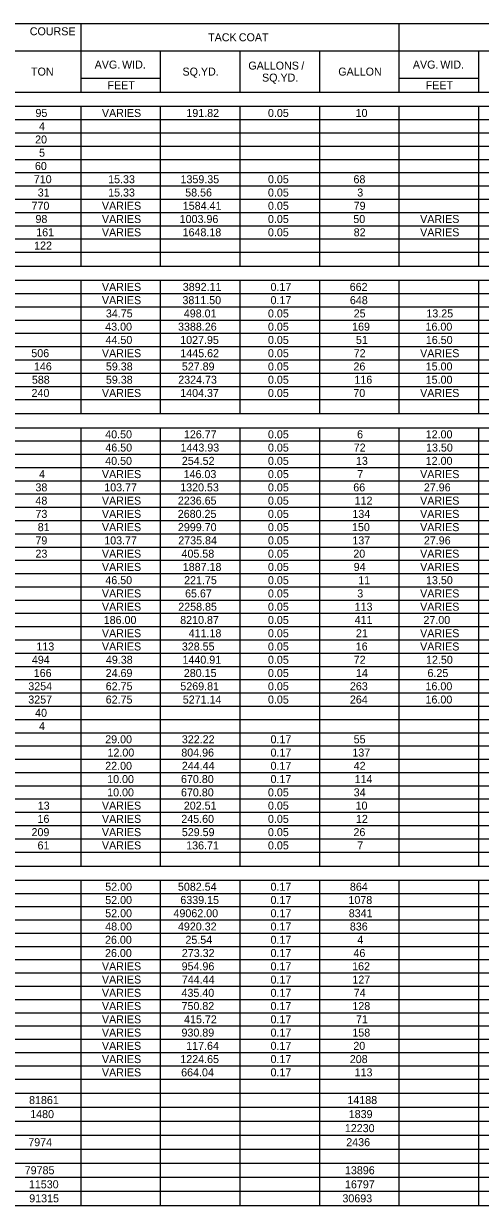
# Model space of a CAD drawing. Extents: x 1226567 to 1228151, y 151309 to 152305.
# Drawn here: x 1226930 to 1227158, y 151665 to 152255 of the extents above; entities that cross this region are included whole.
import ezdxf

# ---------------------------------------------------------------- set-up
doc = ezdxf.new("R2010")
doc.units = 0
doc.layers.add('R_Dimension', color=7, linetype='Continuous')

msp = doc.modelspace()

# ---------------------------------------------------------------- linework, layer by layer
at = {"layer": 'R_Dimension'}
for p, q in [((1226566.84, 152254.68), (1228150.79, 152254.68)), ((1226959.03, 152220.4), (1226959.03, 152254.68)), ((1227117.93, 152220.4), (1227117.93, 152254.68)), ((1226879.58, 152241.04), (1228150.79, 152241.04)), ((1226998.76, 152220.4), (1226998.76, 152241.04)), ((1227038.48, 152220.4), (1227038.48, 152241.04)), ((1227078.21, 152220.4), (1227078.21, 152241.04)), ((1227157.66, 152220.4), (1227157.66, 152241.04)), ((1226959.03, 152227.41), (1226998.76, 152227.41)), ((1227117.93, 152227.41), (1227157.66, 152227.41)), ((1226566.84, 152220.4), (1228150.79, 152220.4)), ((1226566.84, 152220.4), (1228150.79, 152220.4)), ((1226879.58, 152220.4), (1226998.76, 152220.4)), ((1226998.76, 152220.4), (1227157.66, 152220.4)), ((1227157.66, 152220.4), (1227396.01, 152220.4)), ((1226566.84, 152213.39), (1228150.79, 152213.39)), ((1226959.03, 152133.55), (1226959.03, 152213.39)), ((1226998.76, 152133.55), (1226998.76, 152213.39)), ((1227038.48, 152133.55), (1227038.48, 152213.39)), ((1227078.21, 152133.55), (1227078.21, 152213.39)), ((1227117.93, 152133.55), (1227117.93, 152213.39)), ((1227157.66, 152133.55), (1227157.66, 152213.39)), ((1226566.84, 152206.77), (1228150.79, 152206.77)), ((1226566.84, 152200.15), (1228150.79, 152200.15)), ((1226566.84, 152193.53), (1228150.79, 152193.53)), ((1226566.84, 152186.91), (1228150.79, 152186.91)), ((1226566.84, 152180.29), (1228150.79, 152180.29)), ((1226566.84, 152173.67), (1228150.79, 152173.67)), ((1226566.84, 152167.05), (1228150.79, 152167.05)), ((1226566.84, 152160.43), (1228150.79, 152160.43)), ((1226566.84, 152153.8), (1228150.79, 152153.8)), ((1226566.84, 152147.18), (1228150.79, 152147.18)), ((1226566.84, 152140.56), (1228150.79, 152140.56)), ((1226566.84, 152133.55), (1228150.79, 152133.55)), ((1226566.84, 152126.54), (1228150.79, 152126.54)), ((1226959.03, 152059.94), (1226959.03, 152126.54)), ((1226998.76, 152059.94), (1226998.76, 152126.54)), ((1227038.48, 152059.94), (1227038.48, 152126.54)), ((1227078.21, 152059.94), (1227078.21, 152126.54)), ((1227117.93, 152059.94), (1227117.93, 152126.54)), ((1227157.66, 152059.94), (1227157.66, 152126.54)), ((1226566.84, 152119.92), (1228150.79, 152119.92)), ((1226566.84, 152113.3), (1228150.79, 152113.3)), ((1226566.84, 152106.68), (1228150.79, 152106.68)), ((1226566.84, 152100.06), (1228150.79, 152100.06)), ((1226566.84, 152093.44), (1228150.79, 152093.44)), ((1226566.84, 152086.82), (1228150.79, 152086.82)), ((1226566.84, 152080.2), (1228150.79, 152080.2)), ((1226566.84, 152073.58), (1228150.79, 152073.58)), ((1226566.84, 152066.95), (1228150.79, 152066.95)), ((1226566.84, 152059.94), (1228150.79, 152059.94)), ((1226566.84, 152052.93), (1228150.79, 152052.93)), ((1226959.03, 151834.06), (1226959.03, 152052.93)), ((1226998.76, 151834.06), (1226998.76, 152052.93)), ((1227038.48, 151834.06), (1227038.48, 152052.93)), ((1227078.21, 151834.06), (1227078.21, 152052.93)), ((1227117.93, 151834.06), (1227117.93, 152052.93)), ((1227157.66, 151834.06), (1227157.66, 152052.93)), ((1226566.84, 152046.31), (1228150.79, 152046.31)), ((1226566.84, 152039.69), (1228150.79, 152039.69)), ((1226566.84, 152033.07), (1228150.79, 152033.07)), ((1226566.84, 152026.45), (1228150.79, 152026.45)), ((1226566.84, 152019.83), (1228150.79, 152019.83)), ((1226566.84, 152013.21), (1228150.79, 152013.21)), ((1226566.84, 152006.59), (1228150.79, 152006.59)), ((1226566.84, 151999.97), (1228150.79, 151999.97)), ((1226566.84, 151993.35), (1228150.79, 151993.35)), ((1226566.84, 151986.73), (1228150.79, 151986.73)), ((1226566.84, 151980.1), (1228150.79, 151980.1)), ((1226566.84, 151973.48), (1228150.79, 151973.48)), ((1226566.84, 151966.86), (1228150.79, 151966.86)), ((1226566.84, 151960.24), (1228150.79, 151960.24)), ((1226566.84, 151953.62), (1228150.79, 151953.62)), ((1226566.84, 151947), (1228150.79, 151947)), ((1226566.84, 151940.38), (1228150.79, 151940.38)), ((1226566.84, 151933.76), (1228150.79, 151933.76)), ((1226566.84, 151927.14), (1228150.79, 151927.14)), ((1226566.84, 151920.52), (1228150.79, 151920.52)), ((1226566.84, 151913.9), (1228150.79, 151913.9)), ((1226566.84, 151907.27), (1228150.79, 151907.27)), ((1226566.84, 151900.65), (1228150.79, 151900.65)), ((1226566.84, 151894.03), (1228150.79, 151894.03)), ((1226566.84, 151887.41), (1228150.79, 151887.41)), ((1226566.84, 151880.79), (1228150.79, 151880.79)), ((1226566.84, 151874.17), (1228150.79, 151874.17)), ((1226566.84, 151867.55), (1228150.79, 151867.55)), ((1226566.84, 151860.93), (1228150.79, 151860.93)), ((1226566.84, 151854.31), (1228150.79, 151854.31)), ((1226566.84, 151847.69), (1228150.79, 151847.69)), ((1226566.84, 151841.07), (1228150.79, 151841.07)), ((1226566.84, 151834.06), (1228150.79, 151834.06)), ((1226566.84, 151827.05), (1228150.79, 151827.05)), ((1226959.03, 151664.64), (1226959.03, 151827.05)), ((1226998.76, 151664.64), (1226998.76, 151827.05)), ((1227038.48, 151664.64), (1227038.48, 151827.05)), ((1227078.21, 151664.64), (1227078.21, 151827.05)), ((1227117.93, 151664.64), (1227117.93, 151827.05)), ((1227157.66, 151664.64), (1227157.66, 151827.05)), ((1226566.84, 151820.42), (1228150.79, 151820.42)), ((1226566.84, 151813.8), (1228150.79, 151813.8)), ((1226566.84, 151807.18), (1228150.79, 151807.18)), ((1226566.84, 151800.56), (1228150.79, 151800.56)), ((1226566.84, 151793.94), (1228150.79, 151793.94)), ((1226566.84, 151787.32), (1228150.79, 151787.32)), ((1226566.84, 151780.7), (1228150.79, 151780.7)), ((1226566.84, 151774.08), (1228150.79, 151774.08)), ((1226566.84, 151767.46), (1228150.79, 151767.46)), ((1226566.84, 151760.84), (1228150.79, 151760.84)), ((1226566.84, 151754.22), (1228150.79, 151754.22)), ((1226566.84, 151747.6), (1228150.79, 151747.6)), ((1226566.84, 151740.97), (1228150.79, 151740.97)), ((1226566.84, 151734.35), (1228150.79, 151734.35)), ((1226566.84, 151727.73), (1228150.79, 151727.73)), ((1226566.84, 151720.72), (1228150.79, 151720.72)), ((1226566.84, 151713.71), (1228150.79, 151713.71)), ((1226566.84, 151706.7), (1228150.79, 151706.7)), ((1226566.84, 151699.69), (1228150.79, 151699.69)), ((1226566.84, 151692.68), (1228150.79, 151692.68)), ((1226566.84, 151685.67), (1228150.79, 151685.67)), ((1226566.84, 151678.66), (1228150.79, 151678.66)), ((1226566.84, 151671.65), (1228150.79, 151671.65)), ((1226566.84, 151664.64), (1228150.79, 151664.64))]:
    msp.add_line(p, q, dxfattribs=at)

# ---------------------------------------------------------------- texts
for s, height, p in [(' COURSE', 3.994, (1226931.92, 152248.86)), ('TACK', 3.994, (1227022.47, 152245.86)), (' COAT', 3.994, (1227036.31, 152245.86)), ('AVG.', 3.994, (1226965.8, 152232.23)), (' WID.', 3.994, (1226978, 152232.23)), ('GALLONS', 3.994, (1227042.56, 152231.72)), (' /', 3.994, (1227067.53, 152231.72)), ('AVG.', 3.994, (1227124.7, 152232.23)), (' WID.', 3.994, (1227136.9, 152232.23)), ('TON', 3.994, (1226934.03, 152228.73)), ('SQ.YD.', 3.994, (1227009.66, 152228.73)), ('SQ.YD.', 3.994, (1227049.38, 152225.73)), ('GALLON', 3.994, (1227087.46, 152228.73)), ('FEET', 3.994, (1226972.21, 152221.91)), ('FEET', 3.994, (1227131.11, 152221.91)), ('95', 3.994, (1226936.24, 152208.08)), ('VARIES', 3.994, (1226969.43, 152208.08)), ('191.82', 3.994, (1227011.61, 152208.08)), ('0.05', 3.994, (1227052.34, 152208.08)), ('10', 3.994, (1227096.1, 152208.08)), ('4', 3.99, (1226938.04, 152201.46)), ('20', 3.994, (1226936.07, 152194.84)), ('5', 3.99, (1226938.04, 152188.22)), ('60', 3.994, (1226935.98, 152181.6)), ('710', 3.994, (1226935.41, 152174.98)), ('15.33', 3.994, (1226972.54, 152174.98)), ('1359.35', 3.994, (1227008.68, 152174.98)), ('0.05', 3.994, (1227052.34, 152174.98)), ('68', 3.994, (1227095.05, 152174.98)), ('31', 3.994, (1226937.38, 152168.36)), ('15.33', 3.994, (1226972.54, 152168.36)), ('58.56', 3.994, (1227011.02, 152168.36)), ('0.05', 3.994, (1227052.34, 152168.36)), ('3', 3.99, (1227096.94, 152168.36)), ('770', 3.994, (1226934.28, 152161.74)), ('VARIES', 3.994, (1226969.43, 152161.74)), ('1584.41', 3.994, (1227009.81, 152161.74)), ('0.05', 3.994, (1227052.34, 152161.74)), ('79', 3.994, (1227095.13, 152161.74)), ('98', 3.994, (1226936.24, 152155.12)), ('VARIES', 3.994, (1226969.43, 152155.12)), ('1003.96', 3.994, (1227008.26, 152155.12)), ('0.05', 3.994, (1227052.34, 152155.12)), ('50', 3.994, (1227094.97, 152155.12)), ('VARIES', 3.994, (1227128.33, 152155.12)), ('161', 3.994, (1226936.62, 152148.5)), ('VARIES', 3.994, (1226969.43, 152148.5)), ('1648.18', 3.994, (1227009.72, 152148.5)), ('0.05', 3.994, (1227052.34, 152148.5)), ('82', 3.994, (1227095.15, 152148.5)), ('VARIES', 3.994, (1227128.33, 152148.5)), ('122', 3.994, (1226935.58, 152141.88)), ('VARIES', 3.994, (1226969.43, 152121.23)), ('3892.11', 3.994, (1227009.81, 152121.23)), ('0.17', 3.994, (1227053.63, 152121.23)), ('662', 3.994, (1227093.16, 152121.23)), ('VARIES', 3.994, (1226969.43, 152114.61)), ('3811.50', 3.994, (1227009.64, 152114.61)), ('0.17', 3.994, (1227053.63, 152114.61)), ('648', 3.994, (1227093.26, 152114.61)), ('34.75', 3.994, (1226971.41, 152107.99)), ('498.01', 3.994, (1227010.32, 152107.99)), ('0.05', 3.994, (1227052.34, 152107.99)), ('25', 3.994, (1227095.15, 152107.99)), ('13.25', 3.994, (1227131.44, 152107.99)), ('43.00', 3.994, (1226971.08, 152101.37)), ('3388.26', 3.994, (1227007.44, 152101.37)), ('0.05', 3.994, (1227052.34, 152101.37)), ('169', 3.994, (1227094.37, 152101.37)), ('16.00', 3.994, (1227131.02, 152101.37)), ('44.50', 3.994, (1226971.24, 152094.75)), ('1027.95', 3.994, (1227008.52, 152094.75)), ('0.05', 3.994, (1227052.34, 152094.75)), ('51', 3.994, (1227096.28, 152094.75)), ('16.50', 3.994, (1227131.18, 152094.75)), ('506', 3.994, (1226934.18, 152088.13)), ('VARIES', 3.994, (1226969.43, 152088.13)), ('1445.62', 3.994, (1227008.59, 152088.13)), ('0.05', 3.994, (1227052.34, 152088.13)), ('72', 3.994, (1227095.15, 152088.13)), ('VARIES', 3.994, (1227128.33, 152088.13)), ('146', 3.994, (1226935.47, 152081.51)), ('59.38', 3.994, (1226971.41, 152081.51)), ('527.89', 3.994, (1227009.33, 152081.51)), ('0.05', 3.994, (1227052.34, 152081.51)), ('26', 3.994, (1227095.04, 152081.51)), ('15.00', 3.994, (1227131.11, 152081.51)), ('588', 3.994, (1226934.45, 152074.89)), ('59.38', 3.994, (1226971.41, 152074.89)), ('2324.73', 3.994, (1227007.55, 152074.89)), ('0.05', 3.994, (1227052.34, 152074.89)), ('116', 3.994, (1227095.51, 152074.89)), ('15.00', 3.994, (1227131.11, 152074.89)), ('240', 3.994, (1226934.28, 152068.27)), ('VARIES', 3.994, (1226969.43, 152068.27)), ('1404.37', 3.994, (1227008.52, 152068.27)), ('0.05', 3.994, (1227052.34, 152068.27)), ('70', 3.994, (1227094.97, 152068.27)), ('VARIES', 3.994, (1227128.33, 152068.27)), ('40.50', 3.994, (1226971.08, 152047.63)), ('126.77', 3.994, (1227010.38, 152047.63)), ('0.05', 3.994, (1227052.34, 152047.63)), ('6', 3.99, (1227096.83, 152047.63)), ('12.00', 3.994, (1227131.11, 152047.63)), ('46.50', 3.994, (1226971.14, 152041.01)), ('1443.93', 3.994, (1227008.68, 152041.01)), ('0.05', 3.994, (1227052.34, 152041.01)), ('72', 3.994, (1227095.15, 152041.01)), ('13.50', 3.994, (1227131.27, 152041.01)), ('40.50', 3.994, (1226971.08, 152034.38)), ('254.52', 3.994, (1227009.34, 152034.38)), ('0.05', 3.994, (1227052.34, 152034.38)), ('13', 3.994, (1227096.28, 152034.38)), ('12.00', 3.994, (1227131.11, 152034.38)), ('4', 3.99, (1226938.04, 152027.76)), ('VARIES', 3.994, (1226969.43, 152027.76)), ('146.03', 3.994, (1227010.22, 152027.76)), ('0.05', 3.994, (1227052.34, 152027.76)), ('7', 3.99, (1227096.94, 152027.76)), ('VARIES', 3.994, (1227128.33, 152027.76)), ('38', 3.994, (1226936.24, 152021.14)), ('103.77', 3.994, (1226970.59, 152021.14)), ('1320.53', 3.994, (1227008.52, 152021.14)), ('0.05', 3.994, (1227052.34, 152021.14)), ('66', 3.994, (1227094.94, 152021.14)), ('27.96', 3.994, (1227130.2, 152021.14)), ('48', 3.994, (1226936.24, 152014.52)), ('VARIES', 3.994, (1226969.43, 152014.52)), ('2236.65', 3.994, (1227007.36, 152014.52)), ('0.05', 3.994, (1227052.34, 152014.52)), ('112', 3.994, (1227095.62, 152014.52)), ('VARIES', 3.994, (1227128.33, 152014.52)), ('73', 3.994, (1226936.24, 152007.9)), ('VARIES', 3.994, (1226969.43, 152007.9)), ('2680.25', 3.994, (1227007.3, 152007.9)), ('0.05', 3.994, (1227052.34, 152007.9)), ('134', 3.994, (1227094.49, 152007.9)), ('VARIES', 3.994, (1227128.33, 152007.9)), ('81', 3.994, (1226937.38, 152001.28)), ('VARIES', 3.994, (1226969.43, 152001.28)), ('2999.70', 3.994, (1227007.38, 152001.28)), ('0.05', 3.994, (1227052.34, 152001.28)), ('150', 3.994, (1227094.31, 152001.28)), ('VARIES', 3.994, (1227128.33, 152001.28)), ('79', 3.994, (1226936.23, 151994.66)), ('103.77', 3.994, (1226970.59, 151994.66)), ('2735.84', 3.994, (1227007.55, 151994.66)), ('0.05', 3.994, (1227052.34, 151994.66)), ('137', 3.994, (1227094.49, 151994.66)), ('27.96', 3.994, (1227130.2, 151994.66)), ('23', 3.994, (1226936.24, 151988.04)), ('VARIES', 3.994, (1226969.43, 151988.04)), ('405.58', 3.994, (1227009.18, 151988.04)), ('0.05', 3.994, (1227052.34, 151988.04)), ('20', 3.994, (1227094.97, 151988.04)), ('VARIES', 3.994, (1227128.33, 151988.04)), ('VARIES', 3.994, (1226969.43, 151981.42)), ('1887.18', 3.994, (1227009.81, 151981.42)), ('0.05', 3.994, (1227052.34, 151981.42)), ('94', 3.994, (1227095.15, 151981.42)), ('VARIES', 3.994, (1227128.33, 151981.42)), ('46.50', 3.994, (1226971.14, 151974.8)), ('221.75', 3.994, (1227010.47, 151974.8)), ('0.05', 3.994, (1227052.34, 151974.8)), ('11', 3.994, (1227097.41, 151974.8)), ('13.50', 3.994, (1227131.27, 151974.8)), ('VARIES', 3.994, (1226969.43, 151968.18)), ('65.67', 3.994, (1227010.95, 151968.18)), ('0.05', 3.994, (1227052.34, 151968.18)), ('3', 3.99, (1227096.94, 151968.18)), ('VARIES', 3.994, (1227128.33, 151968.18)), ('VARIES', 3.994, (1226969.43, 151961.55)), ('2258.85', 3.994, (1227007.55, 151961.55)), ('0.05', 3.994, (1227052.34, 151961.55)), ('113', 3.994, (1227095.62, 151961.55)), ('VARIES', 3.994, (1227128.33, 151961.55)), ('186.00', 3.994, (1226970.32, 151954.93)), ('8210.87', 3.994, (1227008.52, 151954.93)), ('0.05', 3.994, (1227052.34, 151954.93)), ('411', 3.994, (1227095.62, 151954.93)), ('27.00', 3.994, (1227129.98, 151954.93)), ('VARIES', 3.994, (1226969.43, 151948.31)), ('411.18', 3.994, (1227012.74, 151948.31)), ('0.05', 3.994, (1227052.34, 151948.31)), ('21', 3.994, (1227096.28, 151948.31)), ('VARIES', 3.994, (1227128.33, 151948.31)), ('113', 3.994, (1226936.72, 151941.69)), ('VARIES', 3.994, (1226969.43, 151941.69)), ('328.55', 3.994, (1227009.34, 151941.69)), ('0.05', 3.994, (1227052.34, 151941.69)), ('16', 3.994, (1227096.17, 151941.69)), ('VARIES', 3.994, (1227128.33, 151941.69)), ('494', 3.994, (1226934.45, 151935.07)), ('49.38', 3.994, (1226971.41, 151935.07)), ('1440.91', 3.994, (1227009.66, 151935.07)), ('0.05', 3.994, (1227052.34, 151935.07)), ('72', 3.994, (1227095.15, 151935.07)), ('12.50', 3.994, (1227131.27, 151935.07)), ('166', 3.994, (1226935.38, 151928.45)), ('24.69', 3.994, (1226971.3, 151928.45)), ('280.15', 3.994, (1227010.32, 151928.45)), ('0.05', 3.994, (1227052.34, 151928.45)), ('14', 3.994, (1227096.28, 151928.45)), ('6.25', 3.994, (1227132.01, 151928.45)), ('3254', 3.994, (1226932.66, 151921.83)), ('62.75', 3.994, (1226971.32, 151921.83)), ('5269.81', 3.994, (1227008.59, 151921.83)), ('0.05', 3.994, (1227052.34, 151921.83)), ('263', 3.994, (1227093.26, 151921.83)), ('16.00', 3.994, (1227131.02, 151921.83)), ('3257', 3.994, (1226932.66, 151915.21)), ('62.75', 3.994, (1226971.32, 151915.21)), ('5271.14', 3.994, (1227009.81, 151915.21)), ('0.05', 3.994, (1227052.34, 151915.21)), ('264', 3.994, (1227093.26, 151915.21)), ('16.00', 3.994, (1227131.02, 151915.21)), ('40', 3.994, (1226936.07, 151908.59)), ('4', 3.99, (1226938.04, 151901.97)), ('29.00', 3.994, (1226971.08, 151895.35)), ('322.22', 3.994, (1227009.34, 151895.35)), ('0.17', 3.994, (1227053.63, 151895.35)), ('55', 3.994, (1227095.15, 151895.35)), ('12.00', 3.994, (1226972.21, 151888.73)), ('804.96', 3.994, (1227009.07, 151888.73)), ('0.17', 3.994, (1227053.63, 151888.73)), ('137', 3.994, (1227094.49, 151888.73)), ('22.00', 3.994, (1226971.08, 151882.1)), ('244.44', 3.994, (1227009.34, 151882.1)), ('0.17', 3.994, (1227053.63, 151882.1)), ('42', 3.994, (1227095.15, 151882.1)), ('10.00', 3.994, (1226972.05, 151875.48)), ('670.80', 3.994, (1227008.92, 151875.48)), ('0.17', 3.994, (1227053.63, 151875.48)), ('114', 3.994, (1227095.62, 151875.48)), ('10.00', 3.994, (1226972.05, 151868.86)), ('670.80', 3.994, (1227008.92, 151868.86)), ('0.05', 3.994, (1227052.34, 151868.86)), ('34', 3.994, (1227095.15, 151868.86)), ('13', 3.994, (1226937.38, 151862.24)), ('VARIES', 3.994, (1226969.43, 151862.24)), ('202.51', 3.994, (1227010.32, 151862.24)), ('0.05', 3.994, (1227052.34, 151862.24)), ('10', 3.994, (1227096.1, 151862.24)), ('16', 3.994, (1226937.27, 151855.62)), ('VARIES', 3.994, (1226969.43, 151855.62)), ('245.60', 3.994, (1227009.07, 151855.62)), ('0.05', 3.994, (1227052.34, 151855.62)), ('12', 3.994, (1227096.28, 151855.62)), ('209', 3.994, (1226934.28, 151849)), ('VARIES', 3.994, (1226969.43, 151849)), ('529.59', 3.994, (1227009.33, 151849)), ('0.05', 3.994, (1227052.34, 151849)), ('26', 3.994, (1227095.04, 151849)), ('61', 3.994, (1226937.28, 151842.38)), ('VARIES', 3.994, (1226969.43, 151842.38)), ('136.71', 3.994, (1227011.51, 151842.38)), ('0.05', 3.994, (1227052.34, 151842.38)), ('7', 3.99, (1227096.94, 151842.38)), ('52.00', 3.994, (1226971.08, 151821.74)), ('5082.54', 3.994, (1227007.39, 151821.74)), ('0.17', 3.994, (1227053.63, 151821.74)), ('864', 3.994, (1227093.26, 151821.74)), ('52.00', 3.994, (1226971.08, 151815.12)), ('6339.15', 3.994, (1227008.59, 151815.12)), ('0.17', 3.994, (1227053.63, 151815.12)), ('1078', 3.994, (1227092.53, 151815.12)), ('52.00', 3.994, (1226971.08, 151808.5)), ('49062.00', 3.994, (1227005.17, 151808.5)), ('0.17', 3.994, (1227053.63, 151808.5)), ('8341', 3.994, (1227092.69, 151808.5)), ('48.00', 3.994, (1226971.08, 151801.88)), ('4920.32', 3.994, (1227007.39, 151801.88)), ('0.17', 3.994, (1227053.63, 151801.88)), ('836', 3.994, (1227093.24, 151801.88)), ('26.00', 3.994, (1226970.98, 151795.25)), ('25.54', 3.994, (1227011.13, 151795.25)), ('0.17', 3.994, (1227053.63, 151795.25)), ('4', 3.99, (1227096.94, 151795.25)), ('26.00', 3.994, (1226970.98, 151788.63)), ('273.32', 3.994, (1227009.34, 151788.63)), ('0.17', 3.994, (1227053.63, 151788.63)), ('46', 3.994, (1227095.04, 151788.63)), ('VARIES', 3.994, (1226969.43, 151782.01)), ('954.96', 3.994, (1227009.23, 151782.01)), ('0.17', 3.994, (1227053.63, 151782.01)), ('162', 3.994, (1227094.39, 151782.01)), ('VARIES', 3.994, (1226969.43, 151775.39)), ('744.44', 3.994, (1227009.34, 151775.39)), ('0.17', 3.994, (1227053.63, 151775.39)), ('127', 3.994, (1227094.49, 151775.39)), ('VARIES', 3.994, (1226969.43, 151768.77)), ('435.40', 3.994, (1227009.17, 151768.77)), ('0.17', 3.994, (1227053.63, 151768.77)), ('74', 3.994, (1227095.15, 151768.77)), ('VARIES', 3.994, (1226969.43, 151762.15)), ('750.82', 3.994, (1227009.18, 151762.15)), ('0.17', 3.994, (1227053.63, 151762.15)), ('128', 3.994, (1227094.49, 151762.15)), ('VARIES', 3.994, (1226969.43, 151755.53)), ('415.72', 3.994, (1227010.47, 151755.53)), ('0.17', 3.994, (1227053.63, 151755.53)), ('71', 3.994, (1227096.28, 151755.53)), ('VARIES', 3.994, (1226969.43, 151748.91)), ('930.89', 3.994, (1227009.17, 151748.91)), ('0.17', 3.994, (1227053.63, 151748.91)), ('158', 3.994, (1227094.49, 151748.91)), ('VARIES', 3.994, (1226969.43, 151742.29)), ('117.64', 3.994, (1227011.51, 151742.29)), ('0.17', 3.994, (1227053.63, 151742.29)), ('20', 3.994, (1227094.97, 151742.29)), ('VARIES', 3.994, (1226969.43, 151735.67)), ('1224.65', 3.994, (1227008.59, 151735.67)), ('0.17', 3.994, (1227053.63, 151735.67)), ('208', 3.994, (1227093.2, 151735.67)), ('VARIES', 3.994, (1226969.43, 151729.05)), ('664.04', 3.994, (1227009, 151729.05)), ('0.17', 3.994, (1227053.63, 151729.05)), ('113', 3.994, (1227095.62, 151729.05)), ('81861', 3.994, (1226933.04, 151715.22)), ('14188', 3.994, (1227092.03, 151715.22)), ('1480', 3.994, (1226933.62, 151708.21)), ('1839', 3.994, (1227092.68, 151708.21)), ('12230', 3.994, (1227090.73, 151701.2)), ('7974', 3.994, (1226932.66, 151694.19)), ('2436', 3.994, (1227091.45, 151694.19)), ('79785', 3.994, (1226930.87, 151680.17)), ('13896', 3.994, (1227090.79, 151680.17)), ('11530', 3.994, (1226932.96, 151673.16)), ('16797', 3.994, (1227090.81, 151673.16)), ('91315', 3.994, (1226933.13, 151666.15)), ('30693', 3.994, (1227089.52, 151666.15))]:
    msp.add_text(s, height=height, dxfattribs=at).set_placement(p)

doc.saveas('drawing.dxf')
